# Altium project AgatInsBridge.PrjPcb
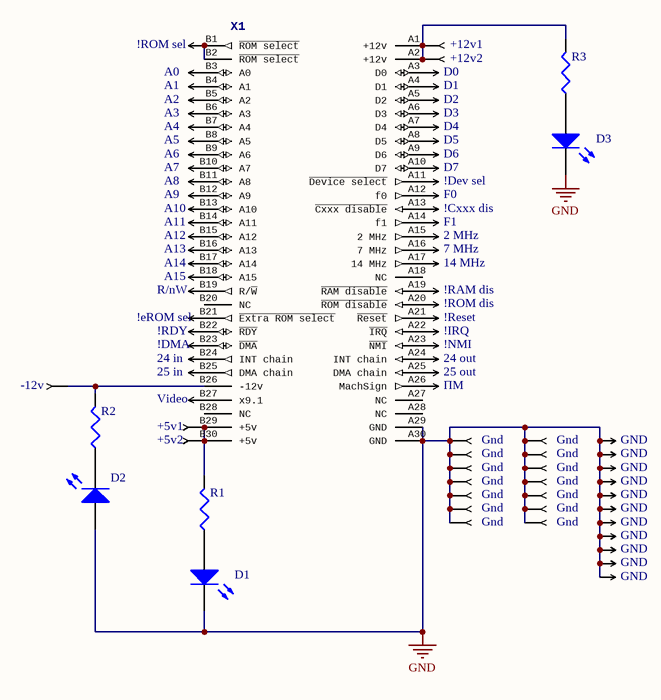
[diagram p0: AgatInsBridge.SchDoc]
1 sheet, 84 parts. Net scope: global (net labels, ports and power ports of the same name join across sheets).
Board file: AgatInsBridge.PcbDoc

## Sheet AgatInsBridge.SchDoc
size A4

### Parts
(Parts that share a designator on the sheet are numbered #1, #2 ... from top to bottom, then left to right.)
2_MHz  Wire pad  [Wire/Stick pad]  (value not drawn)
7_MHz  Wire pad  [Wire/Stick pad]  (value not drawn)
14_MHz  Wire pad  [Wire/Stick pad]  (value not drawn)
24_in  Wire pad  [Wire/Stick pad]  (value not drawn)
24_out  Wire pad  [Wire/Stick pad]  (value not drawn)
25_in  Wire pad  [Wire/Stick pad]  (value not drawn)
25_out  Wire pad  [Wire/Stick pad]  (value not drawn)
!Cxxx_dis  Wire pad  [Wire/Stick pad]  (value not drawn)
!Dev_sel  Wire pad  [Wire/Stick pad]  (value not drawn)
!DMA  Wire pad  [Wire/Stick pad]  (value not drawn)
!eROM_sel  Wire pad  [Wire/Stick pad]  (value not drawn)
!IRQ  Wire pad  [Wire/Stick pad]  (value not drawn)
!NMI  Wire pad  [Wire/Stick pad]  (value not drawn)
!RAM_dis  Wire pad  [Wire/Stick pad]  (value not drawn)
!RDY  Wire pad  [Wire/Stick pad]  (value not drawn)
!Reset  Wire pad  [Wire/Stick pad]  (value not drawn)
!ROM_dis  Wire pad  [Wire/Stick pad]  (value not drawn)
!ROM_sel  Wire pad  [Wire/Stick pad]  (value not drawn)
+5v1  Wire hole  [Wire hole]  (value not drawn)
+5v2  Wire hole  [Wire hole]  (value not drawn)
+12v1  Wire hole  [Wire hole]  (value not drawn)
+12v2  Wire hole  [Wire hole]  (value not drawn)
-12v  Wire hole  [Wire hole]  (value not drawn)
A0  Wire pad  [Wire/Stick pad]  (value not drawn)
A1  Wire pad  [Wire/Stick pad]  (value not drawn)
A2  Wire pad  [Wire/Stick pad]  (value not drawn)
A3  Wire pad  [Wire/Stick pad]  (value not drawn)
A4  Wire pad  [Wire/Stick pad]  (value not drawn)
A5  Wire pad  [Wire/Stick pad]  (value not drawn)
A6  Wire pad  [Wire/Stick pad]  (value not drawn)
A7  Wire pad  [Wire/Stick pad]  (value not drawn)
A8  Wire pad  [Wire/Stick pad]  (value not drawn)
A9  Wire pad  [Wire/Stick pad]  (value not drawn)
A10  Wire pad  [Wire/Stick pad]  (value not drawn)
A11  Wire pad  [Wire/Stick pad]  (value not drawn)
A12  Wire pad  [Wire/Stick pad]  (value not drawn)
A13  Wire pad  [Wire/Stick pad]  (value not drawn)
A14  Wire pad  [Wire/Stick pad]  (value not drawn)
A15  Wire pad  [Wire/Stick pad]  (value not drawn)
D0  Wire pad  [Wire/Stick pad]  (value not drawn)
D1#1  Wire pad  [Wire/Stick pad]  (value not drawn)
D1#2  LED3  [3.5X2.8X1.9]  (value not drawn)
D2#1  Wire pad  [Wire/Stick pad]  (value not drawn)
D2#2  LED3  [3.5X2.8X1.9]  (value not drawn)
D3#1  Wire pad  [Wire/Stick pad]  (value not drawn)
D3#2  LED3  [3.5X2.8X1.9]  (value not drawn)
D4  Wire pad  [Wire/Stick pad]  (value not drawn)
D5  Wire pad  [Wire/Stick pad]  (value not drawn)
D6  Wire pad  [Wire/Stick pad]  (value not drawn)
D7  Wire pad  [Wire/Stick pad]  (value not drawn)
F0  Wire pad  [Wire/Stick pad]  (value not drawn)
F1  Wire pad  [Wire/Stick pad]  (value not drawn)
Gnd#1  Wire hole  [Wire hole]  (value not drawn)
Gnd#2  Wire hole  [Wire hole]  (value not drawn)
GND#3  Wire pad  [Wire/Stick pad]  (value not drawn)
Gnd#4  Wire hole  [Wire hole]  (value not drawn)
Gnd#5  Wire hole  [Wire hole]  (value not drawn)
GND#6  Wire pad  [Wire/Stick pad]  (value not drawn)
Gnd#7  Wire hole  [Wire hole]  (value not drawn)
Gnd#8  Wire hole  [Wire hole]  (value not drawn)
GND#9  Wire pad  [Wire/Stick pad]  (value not drawn)
Gnd#10  Wire hole  [Wire hole]  (value not drawn)
Gnd#11  Wire hole  [Wire hole]  (value not drawn)
GND#12  Wire pad  [Wire/Stick pad]  (value not drawn)
Gnd#13  Wire hole  [Wire hole]  (value not drawn)
Gnd#14  Wire hole  [Wire hole]  (value not drawn)
GND#15  Wire pad  [Wire/Stick pad]  (value not drawn)
Gnd#16  Wire hole  [Wire hole]  (value not drawn)
Gnd#17  Wire hole  [Wire hole]  (value not drawn)
GND#18  Wire pad  [Wire/Stick pad]  (value not drawn)
Gnd#19  Wire hole  [Wire hole]  (value not drawn)
Gnd#20  Wire hole  [Wire hole]  (value not drawn)
GND#21  Wire pad  [Wire/Stick pad]  (value not drawn)
GND#22  Wire pad  [Wire/Stick pad]  (value not drawn)
GND#23  Wire pad  [Wire/Stick pad]  (value not drawn)
GND#24  Wire pad  [Wire/Stick pad]  (value not drawn)
GND#25  Wire pad  [Wire/Stick pad]  (value not drawn)
R1  Res3  [r0805]  (value not drawn)
R2  Res3  [r0805]  (value not drawn)
R3  Res3  [r0805]  (value not drawn)
R/nW  Wire pad  [Wire/Stick pad]  (value not drawn)
Video  Wire pad  [Wire/Stick pad]  (value not drawn)
X1  AGAT_CON  [AGAT_CONP]  (value not drawn)
ПМ  Wire pad  [Wire/Stick pad]  (value not drawn)

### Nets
GND: D1#2.2(K) D2#2.1(A) D3#2.2(K) Gnd#1.0(?) Gnd#2.0(?) GND#3.0(?) Gnd#4.0(?) Gnd#5.0(?) GND#6.0(?) Gnd#7.0(?) Gnd#8.0(?) GND#9.0(?) Gnd#10.0(?) Gnd#11.0(?) GND#12.0(?) Gnd#13.0(?) Gnd#14.0(?) GND#15.0(?) Gnd#16.0(?) Gnd#17.0(?) GND#18.0(?) Gnd#19.0(?) Gnd#20.0(?) GND#21.0(?) GND#22.0(?) GND#23.0(?) GND#24.0(?) GND#25.0(?) X1.A29(GND) X1.A30(GND)
Net2_MHz_0: 2_MHz.0(?) X1.A15(2_MHz)
Net7_MHz_0: 7_MHz.0(?) X1.A16(7_MHz)
Net14_MHz_0: 14_MHz.0(?) X1.A17(14_MHz)
Net24_in_0: 24_in.0(?) X1.B24(INT_chain)
Net24_out_0: 24_out.0(?) X1.A24(INT_chain)
Net25_in_0: 25_in.0(?) X1.B25(DMA_chain)
Net25_out_0: 25_out.0(?) X1.A25(DMA_chain)
Net!Cxxx_dis_0: !Cxxx_dis.0(?) X1.A13(~{Cxxx_disable})
Net!Dev_sel_0: !Dev_sel.0(?) X1.A11(~{Device_select})
Net!DMA_0: !DMA.0(?) X1.B23(~{DMA})
Net!eROM_sel_0: !eROM_sel.0(?) X1.B21(~{Extra_ROM_select})
Net!IRQ_0: !IRQ.0(?) X1.A22(~{IRQ})
Net!NMI_0: !NMI.0(?) X1.A23(~{NMI})
Net!RAM_dis_0: !RAM_dis.0(?) X1.A19(~{RAM_disable})
Net!RDY_0: !RDY.0(?) X1.B22(~{RDY})
Net!Reset_0: !Reset.0(?) X1.A21(~{Reset})
Net!ROM_dis_0: !ROM_dis.0(?) X1.A20(~{ROM_disable})
Net!ROM_sel_0: !ROM_sel.0(?) X1.B1(~{ROM_select}) X1.B2(~{ROM_select})
Net+5v1_0: +5v1.0(?) +5v2.0(?) R1.2 X1.B29(+5v) X1.B30(+5v)
Net+12v1_0: +12v1.0(?) +12v2.0(?) R3.2 X1.A1(+12v) X1.A2(+12v)
Net-12v_0: -12v.0(?) R2.2 X1.B26(-12v)
NetA0_0: A0.0(?) X1.B3(A0)
NetA1_0: A1.0(?) X1.B4(A1)
NetA2_0: A2.0(?) X1.B5(A2)
NetA3_0: A3.0(?) X1.B6(A3)
NetA4_0: A4.0(?) X1.B7(A4)
NetA5_0: A5.0(?) X1.B8(A5)
NetA6_0: A6.0(?) X1.B9(A6)
NetA7_0: A7.0(?) X1.B10(A7)
NetA8_0: A8.0(?) X1.B11(A8)
NetA9_0: A9.0(?) X1.B12(A9)
NetA10_0: A10.0(?) X1.B13(A10)
NetA11_0: A11.0(?) X1.B14(A11)
NetA12_0: A12.0(?) X1.B15(A12)
NetA13_0: A13.0(?) X1.B16(A13)
NetA14_0: A14.0(?) X1.B17(A14)
NetA15_0: A15.0(?) X1.B18(A15)
NetD0_0: D0.0(?) X1.A3(D0)
NetD1#1_0: D1#1.0(?) X1.A4(D1)
NetD1#2_1: D1#2.1(A) R1.1
NetD2#1_0: D2#1.0(?) X1.A5(D2)
NetD2#2_2: D2#2.2(K) R2.1
NetD3#1_0: D3#1.0(?) X1.A6(D3)
NetD3#2_1: D3#2.1(A) R3.1
NetD4_0: D4.0(?) X1.A7(D4)
NetD5_0: D5.0(?) X1.A8(D5)
NetD6_0: D6.0(?) X1.A9(D6)
NetD7_0: D7.0(?) X1.A10(D7)
NetF0_0: F0.0(?) X1.A12(f0)
NetF1_0: F1.0(?) X1.A14(f1)
NetR/nW_0: R/nW.0(?) X1.B19(R/~{W})
NetVideo_0: Video.0(?) X1.B27(x9.1)
NetX1_A26: X1.A26(MachSign) ПМ.0(?)

Not connected (* = marked no-connect by the designer): X1 A18(NC) A27(NC) A28(NC) B20(NC) B28(NC)

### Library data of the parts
D1#2 D2#2 D3#2 = LED3: Typical BLUE SiC LED
R1-R3 = Res3: Resistor; Value: 1K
